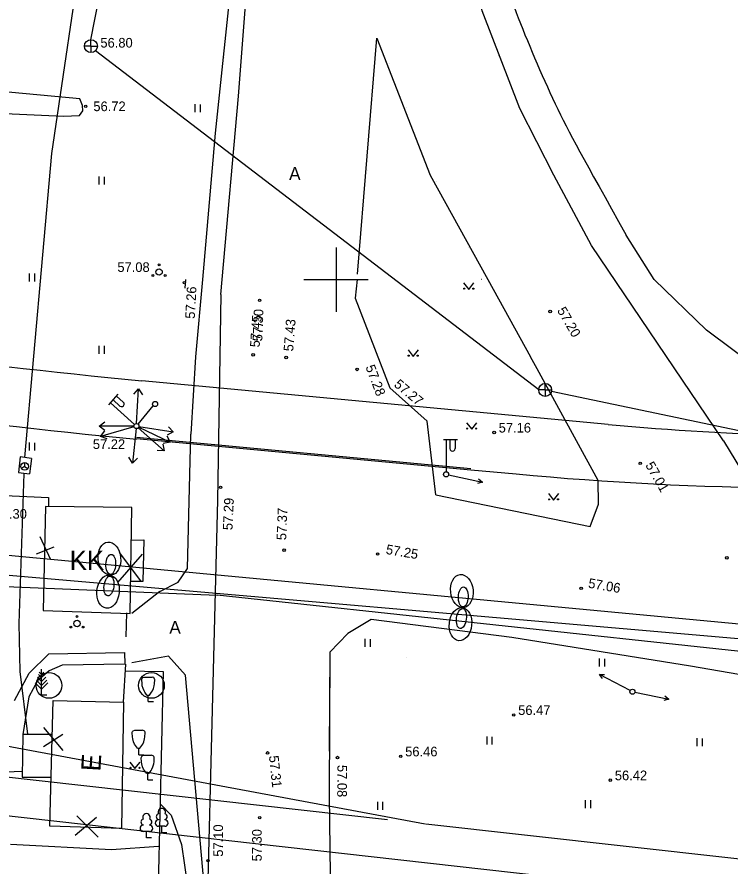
# Model space of a CAD drawing. Extents: x 9156 to 9809, y 2728 to 4000.
# Drawn here: x 9375.2 to 9430.6, y 3704.4 to 3770.4 of the extents above; entities that cross this region are included whole.
import ezdxf

# ---------------------------------------------------------------- set-up
doc = ezdxf.new("R2010")
doc.units = 0
for name, color, linetype in [('Level 16', 7, 'Continuous'), ('Level 17', 7, 'Continuous'), ('Level 18', 7, 'Continuous'), ('Level 21', 7, 'Continuous'), ('Level 54', 7, 'Continuous'), ('Level 56', 7, 'Continuous'), ('Level 8', 7, 'Continuous')]:
    doc.layers.add(name, color=color, linetype=linetype)

msp = doc.modelspace()

# ---------------------------------------------------------------- linework, layer by layer
at = {"layer": 'Level 16'}
msp.add_line((9362.36, 3728.08), (9458.317, 3719.771), dxfattribs=at)
at = {"layer": 'Level 17'}
for p, q in [((9421.148, 3738.747), (9384.912, 3742.147)), ((9403.99, 3708.025), (9324.042, 3716.972)), ((9430.183, 3702.075), (9323.709, 3713.991))]:
    msp.add_line(p, q, dxfattribs=at)
for centre, radius, start, end in [((9431.091, 4234.235), 494.25, 259.71972, 264.63885), ((9439.835, 3937.872), 200, 264.63885, 273.09432)]:
    msp.add_arc(centre, radius, start, end, dxfattribs=at)
at = {"layer": 'Level 18'}
for p, q in [((9410.468, 3735.187), (9384.487, 3737.625)), ((9410.468, 3735.187), (9384.487, 3737.625)), ((9410.477, 3735.29), (9384.497, 3737.728)), ((9410.477, 3735.29), (9384.497, 3737.728)), ((9410.472, 3735.229), (9413.993, 3734.898)), ((9486.214, 3718.077), (9323.495, 3733.347)), ((9363.168, 3726.601), (9390.755, 3725.475)), ((9485.854, 3715.259), (9390.755, 3725.475)), ((9368.264, 3714.916), (9406.926, 3707.698)), ((9430.435, 3705.065), (9406.972, 3707.691))]:
    msp.add_line(p, q, dxfattribs=at)
for centre, radius, start, end in [((9431.091, 4234.235), 498.804, 259.71972, 264.63885), ((9437.352, 3983.805), 250, 264.63885, 274.44386), ((9402.629, 3456.616), 250, 74.8696, 83.61425)]:
    msp.add_arc(centre, radius, start, end, dxfattribs=at)
at = {"layer": 'Level 21'}
for p, q in [((9376.973, 3730.033), (9377.797, 3728.247)), ((9378.071, 3729.209), (9376.698, 3728.659)), ((9383.151, 3728.797), (9384.798, 3726.598)), ((9384.936, 3728.659), (9383.013, 3726.461)), ((9377.247, 3715.195), (9378.758, 3713.409)), ((9378.758, 3714.645), (9377.247, 3713.684)), ((9379.856, 3708.325), (9381.503, 3706.677)), ((9381.366, 3708.188), (9379.719, 3706.814))]:
    msp.add_line(p, q, dxfattribs=at)
for centre in [(9377.687, 3718.465), (9385.649, 3718.465)]:
    msp.add_circle(centre, 1, dxfattribs=at)
at = {"layer": 'Level 54'}
for p, q in [((9380.945, 3768.645), (9389.783, 3813.502)), ((9380.945, 3768.145), (9380.945, 3768.645)), ((9403.169, 3768.759), (9403.169, 3768.759)), ((9380.945, 3768.145), (9380.445, 3768.145)), ((9380.945, 3768.145), (9381.445, 3768.145)), ((9380.945, 3768.145), (9380.945, 3767.645)), ((9415.748, 3741.43), (9381.298, 3767.792)), ((9391.312, 3767.288), (9391.312, 3767.288)), ((9412.603, 3767.426), (9412.603, 3767.426)), ((9404.159, 3766.803), (9404.159, 3766.803)), ((9380.085, 3764.042), (9365.921, 3765.387)), ((9402.794, 3765.043), (9402.794, 3765.043)), ((9380.291, 3763.525), (9380.085, 3764.042)), ((9389.033, 3763.634), (9389.033, 3763.013)), ((9365.887, 3763.318), (9378.813, 3762.698)), ((9380.051, 3762.767), (9380.326, 3763.112)), ((9380.326, 3763.112), (9380.291, 3763.525)), ((9389.438, 3763.622), (9389.438, 3763.013)), ((9405.453, 3763.368), (9405.453, 3763.368)), ((9414.288, 3763.295), (9414.288, 3763.295)), ((9378.813, 3762.698), (9380.051, 3762.767)), ((9390.607, 3761.393), (9390.607, 3761.393)), ((9402.429, 3758.508), (9402.429, 3758.508)), ((9381.557, 3758.013), (9381.557, 3757.393)), ((9381.962, 3758.002), (9381.962, 3757.393)), ((9407.323, 3758.113), (9407.323, 3758.113)), ((9407.823, 3757.596), (9407.823, 3757.596)), ((9389.543, 3752.937), (9389.543, 3752.937)), ((9400, 3752.5), (9400, 3747.5)), ((9410.278, 3752.524), (9410.278, 3752.524)), ((9376.151, 3750.482), (9376.151, 3750)), ((9376.557, 3750.471), (9376.557, 3750)), ((9376.151, 3750), (9376.151, 3749.862)), ((9376.557, 3750), (9376.557, 3749.862)), ((9388.297, 3750), (9388.231, 3749.33)), ((9397.5, 3750), (9402.5, 3750)), ((9397.5, 3750), (9402.5, 3750)), ((9397.5, 3750), (9402.5, 3750)), ((9397.5, 3750), (9402.5, 3750)), ((9400, 3750), (9400, 3747.5)), ((9400, 3750), (9400, 3747.5)), ((9400, 3750), (9400, 3747.5)), ((9401.669, 3750.433), (9401.669, 3750.433)), ((9409.911, 3749.75), (9410.314, 3749.244)), ((9410.314, 3749.244), (9410.711, 3749.75)), ((9401.49, 3748.566), (9401.49, 3748.566)), ((9401.49, 3748.566), (9401.49, 3748.566)), ((9416.631, 3747.529), (9416.631, 3747.529)), ((9381.557, 3744.862), (9381.557, 3744.242)), ((9381.962, 3744.851), (9381.962, 3744.242)), ((9405.591, 3744.544), (9405.994, 3744.039)), ((9405.994, 3744.039), (9406.391, 3744.544)), ((9389.085, 3744.01), (9389.085, 3744.01)), ((9393.559, 3744.152), (9393.559, 3744.152)), ((9396.118, 3743.947), (9396.118, 3743.947)), ((9415.1, 3744.005), (9415.1, 3744.005)), ((9401.63, 3743.024), (9401.63, 3743.024)), ((9420.364, 3734.394), (9415.625, 3743.062)), ((9415.625, 3743.062), (9415.625, 3743.062)), ((9416.248, 3741.43), (9416.248, 3741.93)), ((9384.28, 3741.093), (9384.633, 3741.515)), ((9384.492, 3738.818), (9384.633, 3741.515)), ((9384.633, 3741.515), (9384.941, 3741.059)), ((9404.176, 3741.604), (9404.176, 3741.604)), ((9404.176, 3741.604), (9404.176, 3741.604)), ((9416.248, 3741.43), (9415.748, 3741.43)), ((9416.248, 3741.43), (9416.248, 3741.43)), ((9416.248, 3741.43), (9416.748, 3741.43)), ((9416.248, 3741.43), (9416.248, 3740.93)), ((9427.489, 3741.568), (9427.489, 3741.568)), ((9427.489, 3741.568), (9427.489, 3741.568)), ((9382.339, 3740.275), (9383.075, 3741.093)), ((9382.674, 3740.647), (9383.194, 3740.179)), ((9382.941, 3740.944), (9383.462, 3740.476)), ((9382.473, 3740.423), (9384.333, 3738.752)), ((9384.615, 3738.767), (9385.79, 3740.193)), ((9381.581, 3738.613), (9382.02, 3738.945)), ((9384.281, 3738.618), (9381.581, 3738.613)), ((9382.021, 3738.283), (9381.581, 3738.613)), ((9384.289, 3738.563), (9381.694, 3737.817)), ((9384.679, 3738.588), (9387.346, 3738.17)), ((9386.964, 3738.565), (9387.346, 3738.17)), ((9407.082, 3739.01), (9407.082, 3739.01)), ((9407.082, 3739.01), (9407.082, 3739.01)), ((9410.139, 3738.875), (9410.542, 3738.37)), ((9410.542, 3738.37), (9410.939, 3738.875)), ((9381.694, 3737.817), (9382.025, 3738.256)), ((9384.461, 3738.42), (9384.184, 3735.734)), ((9384.63, 3738.485), (9386.641, 3736.684)), ((9384.662, 3738.532), (9387.097, 3737.366)), ((9387.346, 3738.17), (9386.861, 3737.911)), ((9388.453, 3727.558), (9388.723, 3738.004)), ((9388.723, 3738.004), (9388.723, 3738.004)), ((9412.286, 3738.119), (9412.286, 3738.119)), ((9376.151, 3737.331), (9376.151, 3736.711)), ((9376.557, 3737.32), (9376.557, 3736.711)), ((9382.208, 3737.62), (9381.694, 3737.817)), ((9387.097, 3737.366), (9386.557, 3737.257)), ((9386.843, 3737.854), (9387.097, 3737.366)), ((9408.344, 3737.569), (9409.444, 3737.569)), ((9408.544, 3737.569), (9408.544, 3735.069)), ((9408.844, 3737.569), (9408.844, 3736.869)), ((9409.244, 3737.569), (9409.244, 3736.869)), ((9430.118, 3737.47), (9430.118, 3737.47)), ((9430.118, 3737.47), (9430.118, 3737.47)), ((9386.641, 3736.684), (9386.093, 3736.73)), ((9386.535, 3737.223), (9386.641, 3736.684)), ((9376.332, 3736.113), (9376.182, 3734.899)), ((9384.184, 3735.734), (9383.9, 3736.205)), ((9384.558, 3736.137), (9384.184, 3735.734)), ((9375.792, 3735.486), (9375.542, 3735.319)), ((9375.792, 3735.786), (9375.792, 3735.486)), ((9375.792, 3735.486), (9376.042, 3735.319)), ((9423.64, 3735.726), (9423.64, 3735.726)), ((9408.544, 3734.869), (9408.544, 3734.869)), ((9420.364, 3734.394), (9420.364, 3734.394)), ((9420.394, 3732.552), (9420.364, 3734.394)), ((9420.364, 3734.394), (9420.364, 3734.394)), ((9372.993, 3733.287), (9377.64, 3733.063)), ((9407.754, 3733.284), (9407.754, 3733.284)), ((9407.754, 3733.284), (9419.74, 3730.825)), ((9407.754, 3733.284), (9407.754, 3733.284)), ((9416.501, 3733.371), (9416.904, 3732.865)), ((9416.904, 3732.865), (9417.301, 3733.371)), ((9377.64, 3733.063), (9377.64, 3732.429)), ((9377.42, 3732.371), (9377.234, 3724.28)), ((9384.112, 3732.297), (9377.42, 3732.371)), ((9384, 3724.056), (9384.112, 3732.297)), ((9419.74, 3730.825), (9420.394, 3732.552)), ((9420.394, 3732.552), (9420.394, 3732.552)), ((9420.394, 3732.552), (9420.394, 3732.552)), ((9419.74, 3730.825), (9419.74, 3730.825)), ((9419.74, 3730.825), (9419.74, 3730.825)), ((9384.067, 3729.753), (9385.053, 3729.772)), ((9385.053, 3729.772), (9384.978, 3726.546)), ((9395.957, 3728.981), (9395.957, 3728.981)), ((9403.23, 3728.676), (9403.23, 3728.676)), ((9430.369, 3728.385), (9430.369, 3728.385)), ((9387.722, 3726.498), (9388.453, 3727.558)), ((9388.453, 3727.558), (9388.453, 3727.558)), ((9384.978, 3726.546), (9384.067, 3726.546)), ((9386.297, 3725.761), (9387.722, 3726.498)), ((9387.722, 3726.498), (9387.722, 3726.498)), ((9386.297, 3725.761), (9386.297, 3725.761)), ((9419.043, 3726.014), (9419.043, 3726.014)), ((9377.234, 3724.28), (9384, 3724.056)), ((9383.69, 3722.251), (9383.728, 3724.116)), ((9402.728, 3723.584), (9402.728, 3723.584)), ((9402.728, 3723.584), (9402.728, 3723.584)), ((9400.913, 3722.502), (9400.913, 3722.502)), ((9400.913, 3722.502), (9400.913, 3722.502)), ((9402.243, 3722.073), (9402.243, 3721.453)), ((9413.66, 3722.187), (9413.66, 3722.187)), ((9413.66, 3722.187), (9413.66, 3722.187)), ((9402.648, 3722.061), (9402.648, 3721.453)), ((9376.149, 3719.416), (9377.673, 3720.908)), ((9377.673, 3720.908), (9383.548, 3721.02)), ((9383.548, 3721.02), (9383.585, 3720.125)), ((9399.5, 3721.043), (9399.5, 3721.043)), ((9399.5, 3721.043), (9399.5, 3721.043)), ((9383.585, 3720.125), (9378.714, 3720.05)), ((9383.475, 3717.176), (9383.659, 3720.126)), ((9384.914, 3720.361), (9384.914, 3720.361)), ((9386.983, 3720.736), (9386.983, 3720.736)), ((9405.435, 3720.633), (9405.435, 3720.633)), ((9420.451, 3720.545), (9420.451, 3719.925)), ((9420.856, 3720.534), (9420.856, 3719.925)), ((9377.711, 3719.603), (9376.781, 3718.82)), ((9377.114, 3719.319), (9376.933, 3719.5)), ((9377.114, 3717.719), (9377.114, 3719.719)), ((9377.114, 3719.319), (9377.295, 3719.5)), ((9378.714, 3720.05), (9377.711, 3719.603)), ((9386.598, 3719.525), (9383.624, 3719.562)), ((9385.966, 3693.298), (9386.598, 3719.525)), ((9427.547, 3719.95), (9427.547, 3719.95)), ((9427.547, 3719.95), (9427.547, 3719.95)), ((9374.997, 3717.291), (9376.149, 3719.416)), ((9376.781, 3718.82), (9376.112, 3717.589)), ((9377.114, 3718.469), (9376.703, 3718.879)), ((9377.114, 3718.769), (9376.784, 3719.098)), ((9377.114, 3719.069), (9376.865, 3719.317)), ((9377.114, 3719.069), (9377.363, 3719.317)), ((9377.114, 3718.769), (9377.444, 3719.098)), ((9377.114, 3718.469), (9377.525, 3718.879)), ((9385.101, 3719.118), (9385.701, 3719.118)), ((9388.287, 3719.26), (9388.287, 3719.26)), ((9377.114, 3718.169), (9376.622, 3718.66)), ((9377.114, 3718.169), (9377.606, 3718.66)), ((9376.112, 3717.589), (9375.666, 3714.644)), ((9377.514, 3717.719), (9377.114, 3717.719)), ((9385.301, 3717.718), (9385.501, 3717.718)), ((9385.401, 3717.218), (9385.401, 3717.718)), ((9423.026, 3717.974), (9423.026, 3717.974)), ((9377.748, 3707.522), (9378.008, 3717.291)), ((9378.008, 3717.291), (9383.475, 3717.176)), ((9383.475, 3717.176), (9383.325, 3707.336)), ((9385.401, 3717.218), (9385.801, 3717.218)), ((9413.801, 3716.17), (9413.801, 3716.17)), ((9384.357, 3714.979), (9384.957, 3714.979)), ((9375.666, 3714.644), (9375.591, 3711.325)), ((9377.938, 3714.644), (9375.666, 3714.644)), ((9411.705, 3714.487), (9411.705, 3713.867)), ((9412.111, 3714.476), (9412.111, 3713.867)), ((9428.042, 3714.357), (9428.042, 3713.737)), ((9428.448, 3714.346), (9428.448, 3713.737)), ((9384.557, 3713.579), (9384.757, 3713.579)), ((9384.657, 3713.079), (9384.657, 3713.579)), ((9384.657, 3713.079), (9385.057, 3713.079)), ((9385.063, 3713.04), (9385.663, 3713.04)), ((9394.676, 3713.219), (9394.676, 3713.219)), ((9400.11, 3712.857), (9400.11, 3712.857)), ((9405.019, 3712.951), (9405.019, 3712.951)), ((9383.965, 3712.512), (9384.368, 3712.007)), ((9384.368, 3712.007), (9384.765, 3712.512)), ((9375.591, 3711.773), (9374.365, 3711.735)), ((9385.263, 3711.64), (9385.463, 3711.64)), ((9385.363, 3711.14), (9385.363, 3711.64)), ((9375.591, 3711.325), (9377.849, 3711.325)), ((9385.363, 3711.14), (9385.763, 3711.14)), ((9421.312, 3711.097), (9421.312, 3711.097)), ((9399.457, 3709.921), (9399.457, 3709.921)), ((9419.365, 3709.555), (9419.365, 3708.935)), ((9419.771, 3709.544), (9419.771, 3708.935)), ((9386.355, 3709.239), (9387.173, 3708.381)), ((9403.208, 3709.424), (9403.208, 3708.803)), ((9403.614, 3709.412), (9403.614, 3708.803)), ((9387.173, 3708.381), (9387.991, 3706.107)), ((9385.01, 3707.641), (9385.01, 3707.609)), ((9385.51, 3707.641), (9385.51, 3707.609)), ((9386.199, 3708.051), (9386.199, 3708.019)), ((9386.699, 3708.051), (9386.699, 3708.019)), ((9383.325, 3707.336), (9377.748, 3707.522)), ((9385.51, 3707.109), (9385.01, 3707.109)), ((9385.26, 3706.609), (9385.26, 3707.109)), ((9386.699, 3707.519), (9386.199, 3707.519)), ((9386.449, 3707.019), (9386.449, 3707.519)), ((9386.849, 3707.019), (9386.449, 3707.019)), ((9385.66, 3706.609), (9385.26, 3706.609)), ((9382.543, 3705.698), (9374.698, 3706.109)), ((9386.187, 3705.959), (9382.543, 3705.698)), ((9387.991, 3706.107), (9388.883, 3699.88))]:
    msp.add_line(p, q, dxfattribs=at)
for points in [[(9430.118, 3737.47), (9419.84, 3752.661), (9416.921, 3758.115), (9414.288, 3763.295), (9411.358, 3770.89), (9409.441, 3780.316), (9410.66, 3795.64), (9415.037, 3825.215)], [(9388.093, 3811.627), (9384.276, 3795.068), (9380.436, 3777.191), (9377.873, 3759.795), (9375.78, 3736.18)], [(9393.35, 3787.469), (9390.607, 3761.393), (9389.609, 3750)], [(9391.155, 3750), (9392.427, 3764.251), (9392.975, 3771.674), (9394.934, 3785.155), (9393.35, 3787.469)], [(9401.669, 3750.433), (9403.169, 3768.759), (9407.323, 3758.113), (9411.795, 3750)], [(9424.715, 3750), (9422.553, 3753.458)], [(9389.609, 3750), (9389.085, 3744.01)], [(9391.052, 3748.839), (9391.155, 3750)], [(9401.625, 3750), (9401.49, 3748.566), (9404.176, 3741.604), (9407.082, 3739.01)], [(9401.625, 3750), (9401.49, 3748.566), (9404.176, 3741.604), (9407.082, 3739.01)], [(9411.315, 3750), (9411.306, 3750.016)], [(9411.795, 3750), (9415.1, 3744.005)], [(9489.602, 3731.233), (9475.986, 3733.512), (9461.709, 3735.442), (9447.448, 3737.643), (9439.536, 3739.756), (9432.871, 3743.025), (9428.787, 3746.065), (9424.715, 3750)], [(9391.052, 3748.839), (9390.774, 3732.866), (9389.576, 3685.034), (9388.421, 3681.898), (9386.585, 3673.58), (9386.245, 3667.103), (9386.589, 3648.491)], [(9389.085, 3744.01), (9388.723, 3738.004)], [(9415.625, 3743.062), (9415.1, 3744.005)], [(9416.737, 3741.325), (9476.415, 3728.821)], [(9407.754, 3733.284), (9407.082, 3739.01)], [(9407.754, 3733.284), (9407.082, 3739.01)], [(9430.118, 3737.47), (9432.397, 3733.729), (9434.513, 3729.945), (9437.034, 3727.973), (9440.569, 3726.721), (9451.079, 3725.424), (9464.755, 3723.151), (9479.973, 3720.53), (9493.795, 3717.996)], [(9376.332, 3736.113), (9375.434, 3736.222), (9375.311, 3735.007), (9376.182, 3734.899)], [(9375.74, 3734.932), (9375.342, 3723.275), (9375.425, 3719.559), (9376.011, 3714.682)], [(9408.74, 3734.827), (9411.379, 3734.259)], [(9411.06, 3734.508), (9411.379, 3734.259), (9410.981, 3734.165)], [(9386.297, 3725.761), (9384.133, 3724.066)], [(9470.303, 3712.785), (9456.282, 3715.131), (9442.117, 3717.437), (9427.547, 3719.95), (9413.66, 3722.187), (9402.728, 3723.584), (9400.913, 3722.502), (9399.5, 3721.043), (9399.457, 3709.921), (9399.588, 3699.638)], [(9463.006, 3714.006), (9456.282, 3715.131), (9442.117, 3717.437), (9427.547, 3719.95), (9413.66, 3722.187), (9402.728, 3723.584), (9400.913, 3722.502), (9399.5, 3721.043), (9399.47, 3713.346)], [(9389.966, 3700.611), (9388.287, 3719.26), (9386.983, 3720.736), (9384.115, 3720.216)], [(9385.301, 3717.718), (9385.142, 3717.93), (9385.078, 3718.042), (9385.001, 3718.218), (9384.939, 3718.443), (9384.916, 3718.599), (9384.901, 3718.918), (9384.903, 3718.959), (9384.932, 3719.031), (9384.973, 3719.068), (9385.101, 3719.118)], [(9385.501, 3717.718), (9385.659, 3717.93), (9385.723, 3718.042), (9385.801, 3718.218), (9385.862, 3718.443), (9385.886, 3718.599), (9385.901, 3718.918), (9385.898, 3718.959), (9385.869, 3719.031), (9385.829, 3719.068), (9385.701, 3719.118)], [(9422.849, 3718.067), (9420.459, 3719.324)], [(9420.7, 3718.998), (9420.459, 3719.324), (9420.868, 3719.308)], [(9423.222, 3717.935), (9425.869, 3717.403)], [(9425.547, 3717.647), (9425.869, 3717.403), (9425.473, 3717.303)], [(9384.557, 3713.579), (9384.399, 3713.792), (9384.334, 3713.903), (9384.257, 3714.079), (9384.196, 3714.304), (9384.172, 3714.46), (9384.157, 3714.779), (9384.159, 3714.82), (9384.189, 3714.892), (9384.229, 3714.929), (9384.357, 3714.979)], [(9384.757, 3713.579), (9384.915, 3713.792), (9384.98, 3713.903), (9385.057, 3714.079), (9385.118, 3714.304), (9385.142, 3714.46), (9385.157, 3714.779), (9385.155, 3714.82), (9385.125, 3714.892), (9385.085, 3714.929), (9384.957, 3714.979)], [(9385.263, 3711.64), (9385.105, 3711.853), (9385.04, 3711.965), (9384.963, 3712.14), (9384.902, 3712.365), (9384.878, 3712.521), (9384.863, 3712.84), (9384.865, 3712.881), (9384.895, 3712.953), (9384.935, 3712.99), (9385.063, 3713.04)], [(9385.463, 3711.64), (9385.622, 3711.853), (9385.686, 3711.965), (9385.763, 3712.14), (9385.825, 3712.365), (9385.848, 3712.521), (9385.863, 3712.84), (9385.861, 3712.881), (9385.832, 3712.953), (9385.791, 3712.99), (9385.663, 3713.04)]]:
    msp.add_lwpolyline(points, dxfattribs=at)
for centre, radius in [((9380.945, 3768.145), 0.5), ((9380.548, 3763.464), 0.0909), ((9386.239, 3751.146), 0.0707), ((9386.239, 3750.596), 0.25), ((9385.763, 3750.321), 0.0707), ((9386.715, 3750.321), 0.0707), ((9388.206, 3749.766), 0.0909), ((9409.961, 3749.3), 0.0428), ((9410.661, 3749.3), 0.0452), ((9394.052, 3748.402), 0.0909), ((9416.631, 3747.529), 0.1), ((9393.559, 3744.152), 0.1), ((9396.118, 3743.947), 0.1), ((9405.641, 3744.094), 0.0428), ((9406.341, 3744.094), 0.0452), ((9401.63, 3743.024), 0.1), ((9416.248, 3741.43), 0.5), ((9385.931, 3740.334), 0.199), ((9384.481, 3738.619), 0.2), ((9410.189, 3738.425), 0.0428), ((9410.889, 3738.425), 0.0452), ((9412.286, 3738.119), 0.1), ((9375.792, 3735.486), 0.3), ((9423.64, 3735.726), 0.1), ((9408.544, 3734.869), 0.2), ((9391.02, 3733.861), 0.0909), ((9416.551, 3732.921), 0.0428), ((9417.251, 3732.921), 0.0452), ((9395.957, 3728.981), 0.1), ((9403.23, 3728.676), 0.1), ((9430.369, 3728.385), 0.1), ((9419.043, 3726.014), 0.1), ((9379.865, 3723.274), 0.25), ((9379.865, 3723.824), 0.0707), ((9379.389, 3722.999), 0.0707), ((9380.341, 3722.999), 0.0707), ((9423.026, 3717.974), 0.2), ((9413.801, 3716.17), 0.1), ((9394.676, 3713.219), 0.1), ((9400.11, 3712.857), 0.1), ((9405.019, 3712.951), 0.1), ((9384.015, 3712.062), 0.0428), ((9384.715, 3712.062), 0.0452), ((9421.312, 3711.097), 0.1), ((9394.066, 3708.185), 0.0909), ((9390.055, 3704.844), 0.0909)]:
    msp.add_circle(centre, radius, dxfattribs=at)
for centre, radius, start, end in [((9383.328, 3740.327), 0.2, 227.99553, 48.11692), ((9409.044, 3736.869), 0.2, 179.93931, 0.0607), ((9386.449, 3708.619), 0.292, 332.5799, 207.4201), ((9385.26, 3708.209), 0.292, 332.5799, 207.4201), ((9386.249, 3708.269), 0.224, 105.2441, 257.07903), ((9386.649, 3708.269), 0.224, 282.92097, 74.7559), ((9385.01, 3707.359), 0.25, 90.00001, 270), ((9385.06, 3707.859), 0.224, 105.2441, 257.07903), ((9385.46, 3707.859), 0.224, 282.92097, 74.7559), ((9385.51, 3707.359), 0.25, 270, 89.99999), ((9386.199, 3707.769), 0.25, 90.00001, 270), ((9386.699, 3707.769), 0.25, 270, 89.99999)]:
    msp.add_arc(centre, radius, start, end, dxfattribs=at)
msp.add_open_spline([(9415.976, 3825.147), (9415.093, 3819.866), (9413.578, 3808.546), (9411.641, 3794.709), (9410.924, 3784.763), (9411.76, 3776.853), (9413.792, 3771.101), (9417.009, 3763.374), (9419.226, 3759.393), (9422.553, 3753.458)], degree=3, dxfattribs=at)
at = {"layer": 'Level 56'}
for p, q in [((9421.148, 3738.747), (9384.912, 3742.147)), ((9410.468, 3735.187), (9384.487, 3737.625)), ((9410.468, 3735.187), (9384.487, 3737.625)), ((9410.477, 3735.29), (9384.497, 3737.728)), ((9410.477, 3735.29), (9384.497, 3737.728)), ((9410.472, 3735.229), (9413.993, 3734.898)), ((9486.214, 3718.077), (9323.495, 3733.347)), ((9363.168, 3726.601), (9390.755, 3725.475)), ((9485.854, 3715.259), (9390.755, 3725.475)), ((9403.99, 3708.025), (9324.042, 3716.972)), ((9368.264, 3714.916), (9406.926, 3707.698)), ((9430.183, 3702.075), (9323.709, 3713.991)), ((9430.435, 3705.065), (9406.972, 3707.691))]:
    msp.add_line(p, q, dxfattribs=at)
for centre, radius, start, end in [((9431.091, 4234.235), 494.25, 259.71972, 264.63885), ((9431.091, 4234.235), 498.804, 259.71972, 264.63885), ((9439.835, 3937.872), 200, 264.63885, 273.09432), ((9437.352, 3983.805), 250, 264.63885, 274.44386), ((9402.629, 3456.616), 250, 74.8696, 83.61425)]:
    msp.add_arc(centre, radius, start, end, dxfattribs=at)
at = {"layer": 'Level 8'}
for centre, major_axis, ratio in [((9382.383, 3728.325), (0.134, -1.286), 0.674652), ((9382.383, 3728.325), (0.134, -1.286), 0.674652), ((9382.383, 3728.325), (0.134, -1.286), 0.674652), ((9382.383, 3728.325), (0.134, -1.286), 0.674652), ((9382.49, 3727.869), (-0.027, -0.777), 0.486914), ((9382.49, 3727.869), (-0.027, -0.777), 0.486914), ((9382.49, 3727.869), (-0.027, -0.777), 0.486914), ((9382.49, 3727.869), (-0.027, -0.777), 0.486914), ((9382.276, 3725.752), (0.134, 1.286), 0.674652), ((9382.276, 3725.752), (0.134, 1.286), 0.674652), ((9382.276, 3725.752), (0.134, 1.286), 0.674652), ((9382.276, 3725.752), (0.134, 1.286), 0.674652), ((9382.349, 3726.188), (0.102, 0.771), 0.486914), ((9382.349, 3726.188), (0.102, 0.771), 0.486914), ((9382.349, 3726.188), (0.102, 0.771), 0.486914), ((9382.349, 3726.188), (0.102, 0.771), 0.486914), ((9409.775, 3725.8), (0.134, -1.286), 0.674652), ((9409.775, 3725.8), (0.134, -1.286), 0.674652), ((9409.775, 3725.8), (0.134, -1.286), 0.674652), ((9409.775, 3725.8), (0.134, -1.286), 0.674652), ((9409.882, 3725.344), (-0.027, -0.777), 0.486914), ((9409.882, 3725.344), (-0.027, -0.777), 0.486914), ((9409.882, 3725.344), (-0.027, -0.777), 0.486914), ((9409.882, 3725.344), (-0.027, -0.777), 0.486914), ((9409.668, 3723.227), (0.134, 1.286), 0.674652), ((9409.668, 3723.227), (0.134, 1.286), 0.674652), ((9409.668, 3723.227), (0.134, 1.286), 0.674652), ((9409.668, 3723.227), (0.134, 1.286), 0.674652), ((9409.742, 3723.663), (0.102, 0.771), 0.486914), ((9409.742, 3723.663), (0.102, 0.771), 0.486914), ((9409.742, 3723.663), (0.102, 0.771), 0.486914), ((9409.742, 3723.663), (0.102, 0.771), 0.486914)]:
    msp.add_ellipse(centre, major_axis=major_axis, ratio=ratio, dxfattribs=at)

# ---------------------------------------------------------------- texts
at = {"layer": 'Level 54'}
for s, height, p in [('56.80', 0.75, (9381.682, 3768.035)), ('56.72', 0.75, (9381.136, 3763.095)), ('A', 1, (9396.347, 3757.747)), ('57.08', 0.75, (9383.002, 3750.598)), ('57.16', 0.75, (9412.636, 3738.119)), ('57.22', 0.75, (9381.094, 3736.842)), ('57.30', 0.75, (9373.459, 3731.423)), ('KK', 1.5, (9379.296, 3727.445)), ('A', 1, (9387.037, 3722.482)), ('56.47', 0.75, (9414.151, 3716.17)), ('56.46', 0.75, (9405.369, 3712.951)), ('56.42', 0.75, (9421.662, 3711.097))]:
    msp.add_text(s, height=height, dxfattribs=at).set_placement(p)
for s, height, rotation, p in [('57.26', 0.75, 86.97805, (9389.02, 3746.944)), ('57.20', 0.75, 299.88673, (9417.152, 3747.611)), ('57.45', 0.75, 85.90346, (9394.051, 3744.719)), ('57.30', 0.75, 87.93598, (9394.263, 3745.196)), ('57.43', 0.75, 85.45858, (9396.661, 3744.401)), ('57.28', 0.75, 290.83888, (9402.27, 3743.218)), ('57.27', 0.75, 320.02174, (9404.446, 3741.757)), ('57.01', 0.75, 299.75635, (9424.008, 3735.586)), ('57.29', 0.75, 87.32539, (9391.941, 3730.519)), ('57.37', 0.75, 87.80849, (9396.119, 3729.74)), ('57.25', 0.75, 350.36198, (9403.832, 3728.693)), ('57.06', 0.75, 350.38253, (9419.555, 3726.064)), ('E', 1.5, 86.64331, (9381.678, 3711.757)), ('57.31', 0.75, 276.03156, (9394.779, 3712.981)), ('57.08', 0.75, 269.62476, (9400.104, 3712.289)), ('57.10', 0.75, 90, (9391.21, 3705.154)), ('57.30', 0.75, 90, (9394.219, 3704.79))]:
    msp.add_text(s, height=height, rotation=rotation, dxfattribs=at).set_placement(p)

doc.saveas('drawing.dxf')
